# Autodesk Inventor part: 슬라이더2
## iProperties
Company: 한국ATC센터
Created: 2015-04
Part Number: 슬라이더2
Document SubType Name: Modeling
Designer: KYOUNG IL JANG
Density: 7.85 g/cm^3
Material: 강
Author: KYOUNG IL JANG
